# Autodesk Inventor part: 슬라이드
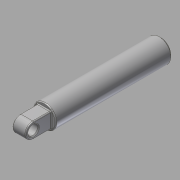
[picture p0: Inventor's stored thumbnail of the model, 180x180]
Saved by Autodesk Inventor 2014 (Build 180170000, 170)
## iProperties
Created: 2016-02
Part Number: 슬라이드
Material: 강철, 연강
Document SubType Name: Modeling
Designer: test
Density: 1 g/cm^3
Appearance: Steel
Author: test
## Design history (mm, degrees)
sketch "스케치2"
  geometry: C1 r 6 at (0, 0); 1 further point
  constraints: 1 centre point, 1 coincident
  dimensions: "d0" = 12 diameter of C1
extrude "돌출1" new body sketch "스케치2" distance "d1" = 60; taper "d2" = 0 deg
hole "구멍1" diameter "d5" = 5.917; stored, may be unused: countersink angle "d9" = 90 deg, drill point angle "d11" = 118 deg; dims "d3" = 10, "d4" = 10, "d6" = 10, "d7" = 4, "d8" = 2, "d10" = 12
chamfer "모따기1" distance "d12" = 1; stored, may be unused: second distance "d13" = 2, angle "d14" = 45 deg
sketch "스케치3"
  geometry: L1 (0, 6)-(0, -6) reference; L2 (0, 4)-(-9, 4); L3 (-9, -4)-(0, -4); L4 (0, -4)-(0, 4); C1 r 2.5 at (-9, 0); A1 r 4 centre (-9, 0) between (-9, 4) and (-9, -4); 2 further points
  constraints: 6 end point, 2 centre point, 2 point on circle, 2 tangent, 1 coincident, 1 horizontal, 1 horizontal alignment, 1 midpoint, 1 parallel, 1 point on line, 1 vertical
  dimensions: "d15" = 13 dimension on A1 L1; "d16" = 8 distance between parallel lines of L3 L2; "d17" = 5 diameter of C1
extrude "돌출2" join sketch "스케치3" stored distance "d18" = 7; taper "d19" = 0 deg
chamfer "모따기2" distance "d20" = 0.5; stored, may be unused: second distance "d21" = 2, angle "d22" = 45 deg
fillet "모깎기1" dims "d23" = 0.5
fillet "모깎기2" dims "d24" = 0.5
fillet "모깎기3" dims "d25" = 0.5
node "솔리드1"
